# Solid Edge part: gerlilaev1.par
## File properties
Author: priit
Template: Normal.par
Last saved by: Anon
Revision: 7
Application: Solid Edge
Accuracy: 0,990
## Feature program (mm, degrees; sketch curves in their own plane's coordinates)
lofted protrusion "unnamed LoftedProtrusion 1"
mirror "unnamed Mirror 1" of "unnamed LoftedProtrusion 1" about plane through (0, 0, 0) normal (1, 0, 0)
lofted protrusion "unnamed LoftedProtrusion 2"
sketch for "ExtrudedProtrusion_2" #1 plane through (0, 0, 0) normal (1, 0, 0) x-axis (0, 1, 0)
  circle centre (25, 12.1007) radius 1.75
sketch for "ExtrudedProtrusion_2" #2 plane through (0, 0, 0) normal (1, 0, 0) x-axis (0, 1, 0)
  circle centre (0, 12.1007) radius 1.75
sketch for "ExtrudedProtrusion_2" #3 plane through (0, 0, 0) normal (1, 0, 0) x-axis (0, 1, 0)
  circle centre (-25, 12.1007) radius 1.75
extrude "ExtrudedProtrusion_2" add finite 55 symmetric
sketch for "ExtrudedProtrusion_3" #1 plane through (0, -25, 0) normal (0, -1, 0) x-axis (1, 0, 0)
  circle centre (-27.5, 12.1007) radius 2.25
sketch for "ExtrudedProtrusion_3" #2 plane through (0, -25, 0) normal (0, -1, 0) x-axis (1, 0, 0)
  circle centre (27.5, 12.1007) radius 2.25
extrude "ExtrudedProtrusion_3" add finite 3.5 symmetric
sketch for "ExtrudedProtrusion_4" #1 plane through (0, 0, 0) normal (0, -1, 0) x-axis (1, 0, 0)
  circle centre (-27.5, 12.1007) radius 2.25
sketch for "ExtrudedProtrusion_4" #2 plane through (0, 0, 0) normal (0, -1, 0) x-axis (1, 0, 0)
  circle centre (27.5, 12.1007) radius 2.25
extrude "ExtrudedProtrusion_4" add finite 3.5 symmetric
sketch for "ExtrudedProtrusion_5" #1 plane through (0, 25, 0) normal (0, -1, 0) x-axis (1, 0, 0)
  circle centre (-27.5, 12.1007) radius 2.25
sketch for "ExtrudedProtrusion_5" #2 plane through (0, 25, 0) normal (0, -1, 0) x-axis (1, 0, 0)
  circle centre (27.5, 12.1007) radius 2.25
extrude "ExtrudedProtrusion_5" add finite 3.5 symmetric
sketch for "ExtrudedCutout_1" #1 plane through (0, -25, 0) normal (0, -1, 0) x-axis (1, 0, 0)
  circle centre (27.5636, 12.0228) radius 1
sketch for "ExtrudedCutout_1" #2 plane through (0, -25, 0) normal (0, -1, 0) x-axis (1, 0, 0)
  circle centre (-27.524, 12.0228) radius 1
extrude "ExtrudedCutout_1" cut finite 112.2852 symmetric
sketch for "ExtrudedProtrusion_6" #1 plane through (0, 0, 20.3256) normal (0, 0, 1) x-axis (1, 0, 0)
  line (-21.1984, 32.853) -> (-21.1984, -30.5147)
  line (-21.1984, -30.5147) -> (-18.7064, -30.5147)
  line (-18.7064, -30.5147) -> (-18.7064, 32.853)
  line (-18.7064, 32.853) -> (-21.1984, 32.853)
sketch for "ExtrudedProtrusion_6" #2 plane through (0, 0, 20.3256) normal (0, 0, 1) x-axis (1, 0, 0)
  line (20.6621, 32.853) -> (20.6621, -30.5147)
  line (20.6621, -30.5147) -> (17.771, -30.5147)
  line (17.771, -30.5147) -> (17.771, 32.853)
  line (17.771, 32.853) -> (20.6621, 32.853)
extrude "ExtrudedProtrusion_6" add finite 3.5 along +normal
sketch for "ExtrudedProtrusion_7" plane through (0, -25, 0) normal (0, -1, 0) x-axis (1, 0, 0)
  circle centre (-21.1984, 21.7158) radius 1.3902
extrude "ExtrudedProtrusion_7" add finite 3.5 symmetric
sketch for "unnamed RevolvedProtrusion 1" plane through (0, -25, 0) normal (0, -1, 0) x-axis (1, 0, 0)
  line (-25.1056, 19.6688) -> (-22.0173, 21.4546)
  line (-22.0173, 21.4546) -> (-22.5549, 22.0202)
  line (-22.5549, 22.0202) -> (-25.4854, 20.3256)
  line (-25.4854, 20.3256) -> (-25.1056, 19.6688)
revolve "unnamed RevolvedProtrusion 1" add finite 360 deg
helix protrusion "HelixProtrusion_1"  Pitch = 1 mm
mirror "unnamed Mirror 2" of "ExtrudedProtrusion_7", "unnamed RevolvedProtrusion 1", "HelixProtrusion_1" about plane through (0, 0, 0) normal (0, -1, 0)
extrude "unnamed Protrusion 1" add finite 3.5 symmetric
revolve "unnamed RevolvedProtrusion 2" add finite 360 deg
helix protrusion "unnamed HelixProtrusion 1"
mirror "unnamed Mirror 3" of "ExtrudedProtrusion_7", "unnamed RevolvedProtrusion 1", "HelixProtrusion_1" about plane through (0, -12.5, 0) normal (0, -1, 0)
extrude "unnamed Protrusion 2" add finite 3.5 symmetric
revolve "unnamed RevolvedProtrusion 3" add finite 360 deg
helix protrusion "unnamed HelixProtrusion 2"
mirror "unnamed Mirror 4" of "ExtrudedProtrusion_7", "unnamed RevolvedProtrusion 1", "HelixProtrusion_1", "unnamed Mirror 3", "unnamed Mirror 2" about plane through (0, 0, 0) normal (1, 0, 0)
extrude "unnamed Protrusion 3" add finite 3.5 symmetric
revolve "unnamed RevolvedProtrusion 4" add finite 360 deg
helix protrusion "unnamed HelixProtrusion 3"
extrude "unnamed Protrusion 4" add finite 3.5 symmetric
revolve "unnamed RevolvedProtrusion 5" add finite 360 deg
helix protrusion "unnamed HelixProtrusion 4"
extrude "unnamed Protrusion 5" add finite 3.5 symmetric
revolve "unnamed RevolvedProtrusion 6" add finite 360 deg
helix protrusion "unnamed HelixProtrusion 5"
fillet "Round_1" radius 1
thinwall "Thinwall_3"  Thickness = 0.25 mm
sketch for "ExtrudedProtrusion_13" #1 plane through (0, 0, 0) normal (1, 0, 0) x-axis (0, 1, 0)
  circle centre (25, 12.1007) radius 1.75
sketch for "ExtrudedProtrusion_13" #2 plane through (0, 0, 0) normal (1, 0, 0) x-axis (0, 1, 0)
  circle centre (0, 12.1007) radius 1.75
sketch for "ExtrudedProtrusion_13" #3 plane through (0, 0, 0) normal (1, 0, 0) x-axis (0, 1, 0)
  circle centre (-25, 12.1007) radius 1.75
extrude "ExtrudedProtrusion_13" add finite 35.5334 symmetric
swept protrusion "unnamed SweptProtrusion 1"
web network "WebNetwork_2"  Profile_Plane1_Distance = 0.6474 mm; Thickness = 0.25 mm
lofted protrusion "unnamed LoftedProtrusion 3"
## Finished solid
Body 1: solid body, 201 faces, 377 edges, 187 vertices, 4 internal voids.
  Faces by surface: plane 115, cylinder 71, spline 13, offset 2
  Edges by curve: line 143, circle 119, intersection 103, spline 10, curve on surface 2
Bounding box of the edges (mm; curved faces can reach further): 59.500 x 100.000 x 29.515, from (-29.75, -50, -5.6893) to (29.75, 50, 23.8256).
Cylindrical faces by radius (mm): R0.5087 x6, R0.75 x4, R0.7587 x6, R1 x10, R1.1402 x6, R1.25 x6, R1.3902 x6, R1.5 x6, R1.75 x9, R2 x6, R2.25 x6
Planar faces by outward normal: +x 7, +y 31, +z 10, -x 7, -y 31, -z 9, oblique 20
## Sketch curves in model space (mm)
circle centre (0, 20.0556, 1.8727) radius 2.9193
circle centre (0, 37.5301, 0.3439) radius 2.9193
circle centre (0, 50, -2.5643) radius 3.125
circle centre (-19.8082, -30.5147, 21.7158) radius 0.9592
spline (-19.9524, -30.5147, 20.3256) -> (0.0872, -45.0203, 20.3256) -> (19.7592, -29.534, 20.3256)
line (-25.4854, -25, 20.3256) -> (-25.1056, -25, 19.6688)
line (-25.1056, -25, 19.6688) -> (-22.0173, -25, 21.4546)
line (-22.0173, -25, 21.4546) -> (-22.5549, -25, 22.0202)
line (-22.5549, -25, 22.0202) -> (-25.4854, -25, 20.3256)
circle centre (-21.1984, -25, 21.7158) radius 1.3902
line (-21.1984, -30.5147, 20.3256) -> (-18.7064, -30.5147, 20.3256)
line (-18.7064, -30.5147, 20.3256) -> (-18.7064, 32.853, 20.3256)
line (-18.7064, 32.853, 20.3256) -> (-21.1984, 32.853, 20.3256)
line (-21.1984, 32.853, 20.3256) -> (-21.1984, -30.5147, 20.3256)
line (20.6621, -30.5147, 20.3256) -> (17.771, -30.5147, 20.3256)
line (17.771, -30.5147, 20.3256) -> (17.771, 32.853, 20.3256)
line (17.771, 32.853, 20.3256) -> (20.6621, 32.853, 20.3256)
line (20.6621, 32.853, 20.3256) -> (20.6621, -30.5147, 20.3256)
circle centre (27.5636, -25, 12.0228) radius 1
circle centre (-27.524, -25, 12.0228) radius 1
circle centre (27.5, 25, 12.1007) radius 2.25
circle centre (-27.5, 25, 12.1007) radius 2.25
circle centre (27.5, 0, 12.1007) radius 2.25
circle centre (-27.5, 0, 12.1007) radius 2.25
circle centre (27.5, -25, 12.1007) radius 2.25
circle centre (-27.5, -25, 12.1007) radius 2.25
circle centre (0, 25, 12.1007) radius 1.75
circle centre (0, 0, 12.1007) radius 1.75
circle centre (0, -25, 12.1007) radius 1.75
line (0, -50, 13.8836) -> (3.1099, -50, 20.3256)
line (0, -50, 20.3256) -> (0, -50, 13.8836)
line (0, -50, 20.3256) -> (3.1099, -50, 20.3256)
spline (0, 0, 0) -> (14.4028, 0, 8.2578) -> (20.6588, 0, 20.3256)
line (0, 0, 20.3256) -> (0, 0, 0)
line (0, 0, 20.3256) -> (20.6588, 0, 20.3256)
spline (0, 50, 0) -> (8.526, 50, 9.6983) -> (15, 50, 20.3256)
line (0, 50, 20.3256) -> (0, 50, 0)
line (0, 50, 20.3256) -> (15, 50, 20.3256)
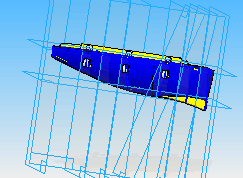
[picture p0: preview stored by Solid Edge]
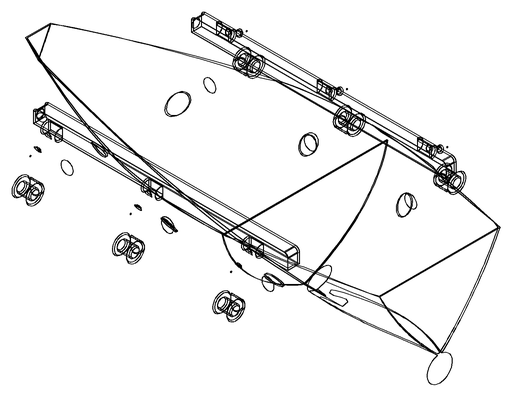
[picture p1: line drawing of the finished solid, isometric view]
